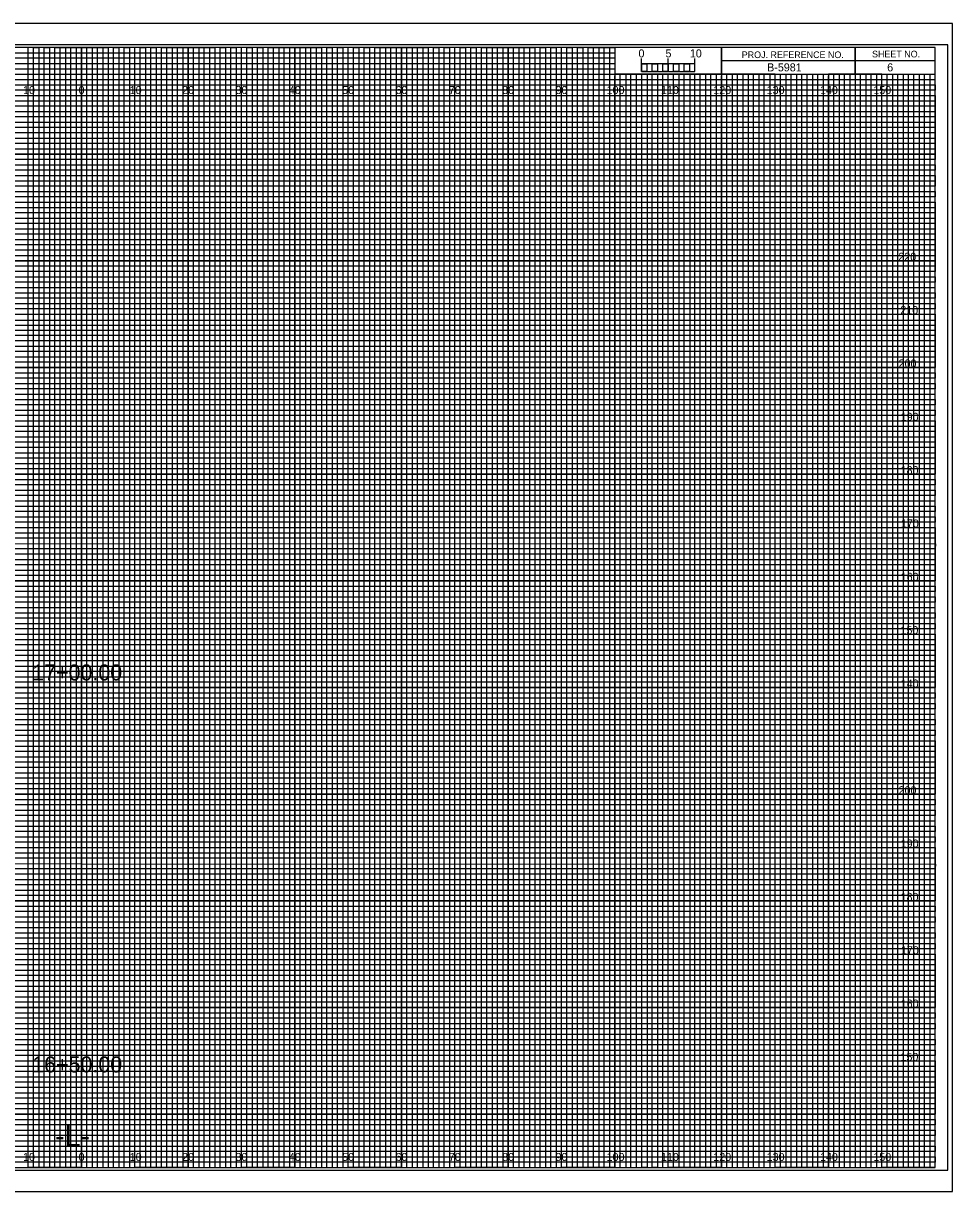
# Model space of a CAD drawing. Extents: x -13 to 323, y -5 to 1754.
# Drawn here: x 149.1 to 323.3, y 435.5 to 654.5 of the extents above; entities that cross this region are included whole.
import ezdxf

# ---------------------------------------------------------------- set-up
doc = ezdxf.new("R2010")
doc.units = 0
for name, color, linetype in [('Exist Cross Section Cell', 7, 'Continuous'), ('Exist XS Center Line Elevation Label', 7, 'Continuous'), ('Exist XS Ground Line', 7, 'Continuous'), ('Prop CMT Concrete Structures', 7, 'Continuous'), ('Prop CMT Guardrail Graphics', 7, 'Continuous'), ('Prop CMT Pvmt Course 1', 7, 'Continuous'), ('Prop CMT Pvmt Course 2', 7, 'Continuous'), ('Prop CMT Pvmt Course 3', 7, 'Continuous'), ('Prop CMT Pvmt Surface', 7, 'Continuous'), ('Prop CMT Shld Paved Course 1', 7, 'Continuous'), ('Prop CMT Shld Paved Course 2', 7, 'Continuous'), ('Prop CMT Shld Paved Course 3', 7, 'Continuous'), ('Prop CMT Subgrade Earthwork', 7, 'Continuous'), ('Prop XS Ditch Standard Text', 7, 'Continuous'), ('Prop XS SE Text', 7, 'Continuous'), ('Prop XS Side Slope Text', 7, 'Continuous'), ('Scratch_Level_0', 7, 'Continuous')]:
    doc.layers.add(name, color=color, linetype=linetype)

msp = doc.modelspace()

# ---------------------------------------------------------------- linework, layer by layer
at = {"layer": 'Exist XS Center Line Elevation Label'}
for points in [[(145, 440), (155, 440), (155, 650), (165, 650), (165, 440), (175, 440), (175, 650), (185, 650), (185, 440), (195, 440), (195, 650), (205, 650), (205, 440), (215, 440), (215, 650), (225, 650), (225, 440), (235, 440), (235, 650), (245, 650), (245, 440), (255, 440), (255, 650), (259.93, 650), (260, 650), (260, 645), (264.99, 645), (264.99, 440), (275, 440), (275, 645), (285, 645), (285, 440), (295, 440), (295, 645), (305, 645), (305, 440), (315, 440), (315, 645)], [(0, 645), (275, 645)], [(0, 625), (320, 625), (320, 635), (0, 635)], [(0, 605), (320, 605), (320, 615), (0, 615)], [(0, 585), (320, 585), (320, 595), (0, 595)], [(0, 565), (320, 565), (320, 575), (0, 575)], [(0, 545), (320, 545), (320, 555), (0, 555)], [(0, 525), (320, 525), (320, 535), (0, 535)], [(0, 505), (320, 505), (320, 515), (0, 515)], [(0, 485), (320, 485), (320, 495), (0, 495)], [(0, 465), (320, 465), (320, 475), (0, 475)], [(0, 445), (320, 445), (320, 455), (0, 455)]]:
    msp.add_lwpolyline(points, dxfattribs=at)
at = {"layer": 'Exist XS Ground Line'}
for p, q in [((150, 650), (140, 650)), ((150, 440), (150, 650)), ((170, 650), (160, 650)), ((160, 650), (160, 440)), ((170, 440), (170, 650)), ((190, 650), (180, 650)), ((180, 650), (180, 440)), ((190, 440), (190, 650)), ((210, 650), (200, 650)), ((200, 650), (200, 440)), ((210, 440), (210, 650)), ((230, 650), (220, 650)), ((220, 650), (220, 440)), ((230, 440), (230, 650)), ((250, 650), (240, 650)), ((240, 650), (240, 440)), ((250, 440), (250, 650)), ((260, 650), (260, 440)), ((270, 440), (270, 645)), ((290, 645), (280, 645)), ((280, 645), (280, 440)), ((290, 440), (290, 645)), ((310, 645), (300, 645)), ((300, 645), (300, 440)), ((310, 440), (310, 645)), ((160, 440), (150, 440)), ((180, 440), (170, 440)), ((200, 440), (190, 440)), ((220, 440), (210, 440)), ((240, 440), (230, 440)), ((260, 440), (250, 440)), ((280, 440), (270, 440)), ((300, 440), (290, 440)), ((320, 440), (310, 440)), ((320, 440), (320, 440))]:
    msp.add_line(p, q, dxfattribs=at)
for points in [[(0, 640), (320, 640), (320, 630), (0, 630)], [(0, 620), (320, 620), (320, 610), (0, 610)], [(0, 600), (320, 600), (320, 590), (0, 590)], [(0, 580), (320, 580), (320, 570), (0, 570)], [(0, 560), (320, 560), (320, 550), (0, 550)], [(0, 540), (320, 540), (320, 530), (0, 530)], [(0, 520), (320, 520), (320, 510), (0, 510)], [(0, 500), (320, 500), (320, 490), (0, 490)], [(0, 480), (320, 480), (320, 470), (0, 470)], [(0, 460), (320, 460), (320, 450), (0, 450)]]:
    msp.add_lwpolyline(points, dxfattribs=at)
at = {"layer": 'Prop CMT Pvmt Course 1'}
for p, q in [((323.3, 654.5), (-13.4, 654.5)), ((-13.4, 435.5), (323.3, 435.5))]:
    msp.add_line(p, q, dxfattribs=at)
at = {"layer": 'Prop CMT Pvmt Course 2'}
msp.add_lwpolyline([(-13.4, 435.5), (323.3, 435.5), (323.3, 654.5), (-13.4, 654.5)], close=True, dxfattribs=at)
at = {"layer": 'Prop CMT Pvmt Course 3'}
msp.add_lwpolyline([(-10.8, 439.5), (322.4, 439.5), (322.4, 650.5), (-10.8, 650.5)], close=True, dxfattribs=at)
at = {"layer": 'Prop CMT Shld Paved Course 1'}
for p, q in [((305, 650), (305, 645)), ((305, 645), (305, 650)), ((280, 647.5), (280, 645)), ((320, 647.49), (280, 647.49)), ((280, 645), (320, 645))]:
    msp.add_line(p, q, dxfattribs=at)
for points in [[(320, 650), (0, 650), (0, 440), (320, 440)], [(280, 650), (260, 650), (260, 645.03), (280, 645.03)], [(320, 650), (280, 650), (280, 645), (320, 645)]]:
    msp.add_lwpolyline(points, close=True, dxfattribs=at)
at = {"layer": 'Prop CMT Shld Paved Course 2'}
for p, q in [((267, 645), (266.01, 645)), ((266.01, 645), (266.01, 440)), ((267, 440), (267, 645)), ((269, 645), (268, 645)), ((268, 645), (268, 440)), ((269, 440), (269, 645)), ((266.01, 440), (265, 440)), ((268, 440), (267, 440))]:
    msp.add_line(p, q, dxfattribs=at)
for points in [[(150, 440), (151, 440), (151, 650), (152, 650), (152, 440)], [(152, 440), (153, 440), (153, 650), (154, 650), (154, 440)], [(155, 440), (156, 440), (156, 650), (157, 650), (157, 440)], [(157, 440), (158, 440), (158, 650), (159, 650), (159, 440)], [(160, 440), (161, 440), (161, 650), (162, 650), (162, 440)], [(162, 440), (163, 440), (163, 650), (164, 650), (164, 440)], [(165, 440), (166, 440), (166, 650), (167, 650), (167, 440)], [(167, 440), (168, 440), (168, 650), (169, 650), (169, 440)], [(170, 440), (171, 440), (171, 650), (172, 650), (172, 440)], [(172, 440), (173, 440), (173, 650), (174, 650), (174, 440)], [(175, 440), (176, 440), (176, 650), (177, 650), (177, 440)], [(177, 440), (178, 440), (178, 650), (179, 650), (179, 440)], [(180, 440), (181, 440), (181, 650), (182, 650), (182, 440)], [(182, 440), (183, 440), (183, 650), (184, 650), (184, 440)], [(185, 440), (186, 440), (186, 650), (187, 650), (187, 440)], [(187, 440), (188, 440), (188, 650), (189, 650), (189, 440)], [(190, 440), (191, 440), (191, 650), (192, 650), (192, 440)], [(192, 440), (193, 440), (193, 650), (194, 650), (194, 440)], [(195, 440), (196, 440), (196, 650), (197, 650), (197, 440)], [(197, 440), (198, 440), (198, 650), (199, 650), (199, 440)], [(200, 440), (201, 440), (201, 650), (202, 650), (202, 440)], [(202, 440), (203, 440), (203, 650), (204, 650), (204, 440)], [(205, 440), (206, 440), (206, 650), (207, 650), (207, 440)], [(207, 440), (208, 440), (208, 650), (209, 650), (209, 440)], [(210, 440), (211, 440), (211, 650), (212, 650), (212, 440)], [(212, 440), (213, 440), (213, 650), (214, 650), (214, 440)], [(215, 440), (216, 440), (216, 650), (217, 650), (217, 440)], [(217, 440), (218, 440), (218, 650), (219, 650), (219, 440)], [(220, 440), (221, 440), (221, 650), (222, 650), (222, 440)], [(222, 440), (223, 440), (223, 650), (224, 650), (224, 440)], [(225, 440), (226, 440), (226, 650), (227, 650), (227, 440)], [(227, 440), (228, 440), (228, 650), (229, 650), (229, 440)], [(230, 440), (231, 440), (231, 650), (232, 650), (232, 440)], [(232, 440), (233, 440), (233, 650), (234, 650), (234, 440)], [(235, 440), (236, 440), (236, 650), (237, 650), (237, 440)], [(237, 440), (238, 440), (238, 650), (239, 650), (239, 440)], [(240, 440), (241, 440), (241, 650), (242, 650), (242, 440)], [(242, 440), (243, 440), (243, 650), (244, 650), (244, 440)], [(245, 440), (246, 440), (246, 650), (247, 650), (247, 440)], [(247, 440), (248, 440), (248, 650), (249, 650), (249, 440)], [(250, 440), (251, 440), (251, 650), (252, 650), (252, 440)], [(252, 440), (253, 440), (253, 650), (254, 650), (254, 440)], [(255, 440), (256, 440), (256, 650), (257, 650), (257, 440)], [(257, 440), (258, 440), (258, 650), (259, 650), (259, 440)], [(260, 440), (261, 440), (261, 645), (262.02, 645), (262.02, 440)], [(262, 440), (263, 440), (263, 645), (263.99, 645), (263.99, 440)], [(270, 440), (270.98, 440), (270.98, 645), (272, 645), (272, 440)], [(272, 440), (273, 440), (273, 645), (274.05, 645), (274.05, 440)], [(275, 440), (276, 440), (276, 645), (277, 645), (277, 440)], [(277, 440), (278, 440), (278, 645), (279, 645), (279, 440)], [(280, 440), (281, 440), (281, 645), (282, 645), (282, 440)], [(282, 440), (283, 440), (283, 645), (284, 645), (284, 440)], [(285, 440), (286, 440), (286, 645), (287, 645), (287, 440)], [(287, 440), (288, 440), (288, 645), (289, 645), (289, 440)], [(290, 440), (291, 440), (291, 645), (292, 645), (292, 440)], [(292, 440), (293, 440), (293, 645), (294, 645), (294, 440)], [(295, 440), (296, 440), (296, 645), (297, 645), (297, 440)], [(297, 440), (298, 440), (298, 645), (299, 645), (299, 440)], [(300, 440), (301, 440), (301, 645), (302, 645), (302, 440)], [(302, 440), (303, 440), (303, 645), (304, 645), (304, 440)], [(305, 440), (306, 440), (306, 645), (307, 645), (307, 440)], [(307, 440), (308, 440), (308, 645), (309, 645), (309, 440)], [(310, 440), (311, 440), (311, 645), (312, 645), (312, 440)], [(312, 440), (313, 440), (313, 645), (314, 645), (314, 440)], [(315, 440), (316, 440), (316, 645), (317, 645), (317, 440)], [(317, 440), (318, 440), (318, 645), (319, 645), (319, 440)]]:
    msp.add_lwpolyline(points, dxfattribs=at)
at = {"layer": 'Prop CMT Shld Paved Course 3'}
for p, q in [((265, 645.49), (265, 647.9)), ((265, 646.9), (265, 647.9)), ((270, 645.49), (270, 647.9)), ((275, 645.49), (275, 647.9)), ((275, 646.9), (275, 647.9))]:
    msp.add_line(p, q, dxfattribs=at)
for points in [[(275, 646.9), (265, 646.9), (265, 645.49), (275, 645.49)], [(265, 646.9), (266, 646.9), (266, 645.49), (265, 645.49)], [(267, 646.9), (268, 646.9), (268, 645.49), (267, 645.49)], [(269, 646.9), (270, 646.9), (270, 645.49), (269, 645.49)], [(271, 646.9), (272, 646.9), (272, 645.49), (271, 645.49)], [(273, 646.9), (274, 646.9), (274, 645.49), (273, 645.49)]]:
    msp.add_lwpolyline(points, close=True, dxfattribs=at)
at = {"layer": 'Prop CMT Subgrade Earthwork'}
for p, q in [((150, 440), (150, 650)), ((160, 440), (160, 650)), ((170, 440), (170, 650)), ((180, 440), (180, 650)), ((190, 440), (190, 650)), ((200, 440), (200, 650)), ((210, 440), (210, 650)), ((220, 440), (220, 650)), ((230, 440), (230, 650)), ((240, 440), (240, 650)), ((250, 440), (250, 650)), ((260, 440), (260, 644.69)), ((270, 440), (270, 644.69)), ((280, 440), (280, 644.69)), ((290, 440), (290, 644.69)), ((300, 440), (300, 644.69)), ((310, 440), (310, 644.69)), ((0, 640), (320, 640)), ((0, 630), (320, 630)), ((0, 620), (320, 620)), ((0, 610), (320, 610)), ((0, 600), (320, 600)), ((0, 590), (320, 590)), ((0, 580), (320, 580)), ((0, 570), (320, 570)), ((0, 560), (320, 560)), ((0, 550), (320, 550)), ((0, 540), (320, 540)), ((0, 530), (320, 530)), ((0, 520), (320, 520)), ((0, 510), (320, 510)), ((0, 500), (320, 500)), ((0, 490), (320, 490)), ((0, 480), (320, 480)), ((0, 470), (320, 470)), ((0, 460), (320, 460)), ((0, 450), (320, 450))]:
    msp.add_line(p, q, dxfattribs=at)
at = {"layer": 'Scratch_Level_0'}
for p, q in [((0, 649), (260, 649)), ((260, 649), (260, 647.98)), ((260, 647.98), (0, 647.98)), ((0, 647), (260, 647)), ((260, 647), (260, 645.89)), ((260, 645.89), (0, 645.89)), ((0, 644), (320, 644))]:
    msp.add_line(p, q, dxfattribs=at)
for points in [[(0, 643), (270, 643), (320, 643), (320, 642), (0, 642)], [(0, 641), (320, 641), (320, 639), (0, 639)], [(0, 638), (320, 638), (320, 637), (0, 636.98)], [(0, 636), (320, 636), (320, 634), (0, 634)], [(0, 633), (320, 633), (320, 632), (0, 632)], [(0, 631), (320, 631), (320, 629), (0, 629)], [(0, 628), (320, 628), (320, 627), (0, 627)], [(0, 626), (320, 626), (320, 624), (0, 624)], [(0, 623), (320, 623), (320, 622), (0, 622)], [(0, 621), (320, 621), (320, 619), (0, 619)], [(0, 618), (320, 618), (320, 617), (0, 617)], [(0, 616), (320, 616), (320, 613.95), (320, 613), (320, 612), (0, 612)], [(0, 614), (320, 614), (320, 613), (0, 613)], [(0, 611), (320, 611), (320, 609), (0, 609.03)], [(0, 609.03), (320, 609), (320, 608), (0, 608)], [(0, 607), (320, 607), (320, 606), (0, 606)], [(0, 604), (320, 604), (320, 603), (0, 603)], [(0, 602), (320, 602), (320, 601), (0, 601)], [(-0.07, 598.89), (320, 598.89), (320, 597.88), (-0.07, 597.88)], [(0, 597), (320, 597), (320, 596), (0, 596)], [(0, 594), (320, 594), (320, 593), (0, 593)], [(0, 592), (320, 592), (320, 591), (0, 591)], [(0, 589), (320, 589), (320, 588), (0, 588)], [(0, 587), (320, 587), (320, 586), (0, 586)], [(0, 584), (320, 584), (320, 583), (0, 583)], [(0, 582), (320, 582), (320, 581), (0, 581)], [(0, 579), (320, 579), (319.99, 577.98), (0, 578)], [(0, 577), (320, 577), (320, 576), (0, 576)], [(0, 574), (320, 574), (320, 573), (0, 573)], [(0, 572), (320, 572), (320, 571), (0, 571)], [(0, 569), (320, 569), (320, 568), (0, 568)], [(0, 567), (320, 567), (320, 566), (0, 566)], [(0, 564), (320, 564), (320, 563), (0, 563)], [(0, 562), (320, 562), (320, 561), (0, 561)], [(0, 559), (320, 559), (320, 558), (0, 558)], [(0, 556.99), (320.07, 556.91), (320, 556), (0, 556)], [(0, 554), (320, 554), (320, 553), (0, 553)], [(0, 552), (320, 552), (320, 551), (0, 551)], [(0, 549), (320, 549), (320, 548), (0, 548)], [(0, 547), (320, 547), (320, 546), (0, 546)], [(0, 544), (320, 544), (320, 543), (0, 543)], [(0, 542), (320, 542), (320, 541), (0, 541)], [(0, 539), (320, 539), (320, 538), (0, 538)], [(0, 537), (320, 537), (320, 536), (0, 536)], [(0, 534), (320, 534), (320, 533), (0, 533)], [(0, 532), (320, 532), (320, 531), (0, 531)], [(0, 529), (320, 529), (320, 528), (0, 528)], [(0, 527), (320, 527), (320, 526), (0, 526)], [(0, 524), (320, 524), (320, 523), (0, 523)], [(0, 522), (320, 522), (320, 521), (0, 521)], [(0, 519), (320, 519), (319.99, 517.98), (0, 518)], [(0, 517), (320, 517), (320, 516), (0, 516)], [(0, 514), (320, 514), (320, 513), (0, 513)], [(0, 512), (320, 512), (320, 511), (0, 511)], [(0, 509), (320, 509), (320, 508), (0, 508)], [(0, 507), (320, 507), (320, 506), (0, 506)], [(0, 504), (320, 504), (320, 503), (0, 503)], [(0, 502), (320, 502), (320, 501), (0, 501)], [(0, 499), (320, 499), (320, 498), (0, 498)], [(0, 496.99), (320.07, 496.91), (320, 496), (0, 496)], [(0, 494), (320, 494), (320, 493), (0, 493)], [(0, 492), (320, 492), (320, 491), (0, 491)], [(0, 489), (320, 489), (320, 488), (0, 488)], [(0, 487), (320, 487), (320, 486), (0, 486)], [(0, 484), (320, 484), (320, 483), (0, 483)], [(0, 482), (320, 482), (320, 481), (0, 481)], [(0, 479), (320, 479), (320, 478), (0, 478)], [(0, 477), (320, 477), (320, 476), (0, 476)], [(0, 474), (320, 474), (320, 473), (0, 473)], [(0, 472), (320, 472), (320, 471), (0, 471)], [(0, 469), (320, 469), (320, 468), (0, 468)], [(0, 467), (320, 467), (320, 466), (0, 466)], [(0, 464), (320, 464), (320, 463), (0, 463)], [(0, 462), (320, 462), (320, 461), (0, 461)], [(0, 459), (320, 459), (320, 458), (0, 458)], [(0, 457), (320, 457), (320, 456), (0, 456)], [(0, 454), (320, 454), (320, 453), (0, 453)], [(0, 452), (320, 452), (320, 451), (0, 451)], [(0, 449), (320, 449), (320, 448), (0, 448)], [(0, 447), (320, 447), (320, 446), (0, 446)], [(0, 444), (320, 444), (320, 443), (0, 443)], [(0, 442), (320, 442), (320, 441), (0, 441)]]:
    msp.add_lwpolyline(points, dxfattribs=at)

# ---------------------------------------------------------------- texts
at = {"layer": 'Exist Cross Section Cell'}
for s, p in [('220', (313.12, 610)), ('210', (313.5, 600)), ('200', (313.17, 590)), ('190', (313.57, 580)), ('180', (313.55, 570)), ('170', (313.61, 560)), ('160', (313.57, 550)), ('150', (313.52, 540)), ('140', (313.57, 530)), ('200', (313.17, 510)), ('190', (313.57, 500)), ('180', (313.55, 490)), ('170', (313.61, 480)), ('160', (313.57, 470)), ('150', (313.52, 460))]:
    msp.add_text(s, height=1.5, dxfattribs=at).set_placement(p)
at = {"layer": 'Prop CMT Concrete Structures'}
msp.add_text('6', height=1.5, dxfattribs=at).set_placement((311.03, 645.5))
at = {"layer": 'Prop CMT Guardrail Graphics'}
for s, p in [('5', (269.47, 648.12)), ('10', (274.04, 648.12))]:
    msp.add_text(s, height=1.5, dxfattribs=at).set_placement(p)
at = {"layer": 'Prop CMT Pvmt Surface'}
for s, p in [('17+00.00', (150.77, 531.33)), ('16+50.00', (150.77, 457.85))]:
    msp.add_text(s, height=3, dxfattribs=at).set_placement(p)
at = {"layer": 'Prop CMT Shld Paved Course 1'}
for s, p in [('PROJ. REFERENCE NO.', (283.77, 647.99)), ('SHEET NO.', (308.19, 648.12))]:
    msp.add_text(s, height=1.25, dxfattribs=at).set_placement(p)
at = {"layer": 'Prop CMT Shld Paved Course 3'}
msp.add_text('0', height=1.5, dxfattribs=at).set_placement((264.41, 648.12))
at = {"layer": 'Prop XS Ditch Standard Text'}
for s, p in [('10', (149.04, 641.25)), ('0', (159.45, 641.25)), ('0', (159.45, 641.25)), ('10', (169.04, 641.25)), ('20', (178.86, 641.25)), ('30', (188.86, 641.25)), ('40', (198.86, 641.25)), ('50', (208.86, 641.25)), ('60', (218.86, 641.25)), ('70', (228.86, 641.25)), ('80', (238.86, 641.25)), ('90', (248.86, 641.25)), ('100', (258.44, 641.25)), ('110', (268.62, 641.25)), ('120', (278.44, 641.25)), ('130', (288.44, 641.25)), ('140', (298.44, 641.25)), ('150', (308.44, 641.25)), ('10', (149.04, 441.25)), ('0', (159.45, 441.25)), ('0', (159.45, 441.25)), ('10', (169.04, 441.25)), ('20', (178.86, 441.25)), ('30', (188.86, 441.25)), ('40', (198.86, 441.25)), ('50', (208.86, 441.25)), ('60', (218.86, 441.25)), ('70', (228.86, 441.25)), ('80', (238.86, 441.25)), ('90', (248.86, 441.25)), ('100', (258.44, 441.25)), ('110', (268.62, 441.25)), ('120', (278.44, 441.25)), ('130', (288.44, 441.25)), ('140', (298.44, 441.25)), ('150', (308.44, 441.25))]:
    msp.add_text(s, height=1.5, dxfattribs=at).set_placement(p)
at = {"layer": 'Prop XS SE Text'}
msp.add_text('-L-', height=4, dxfattribs=at).set_placement((155.06, 444))
at = {"layer": 'Prop XS Side Slope Text'}
msp.add_text('B-5981', height=1.5, dxfattribs=at).set_placement((288.53, 645.5))

doc.saveas('drawing.dxf')
